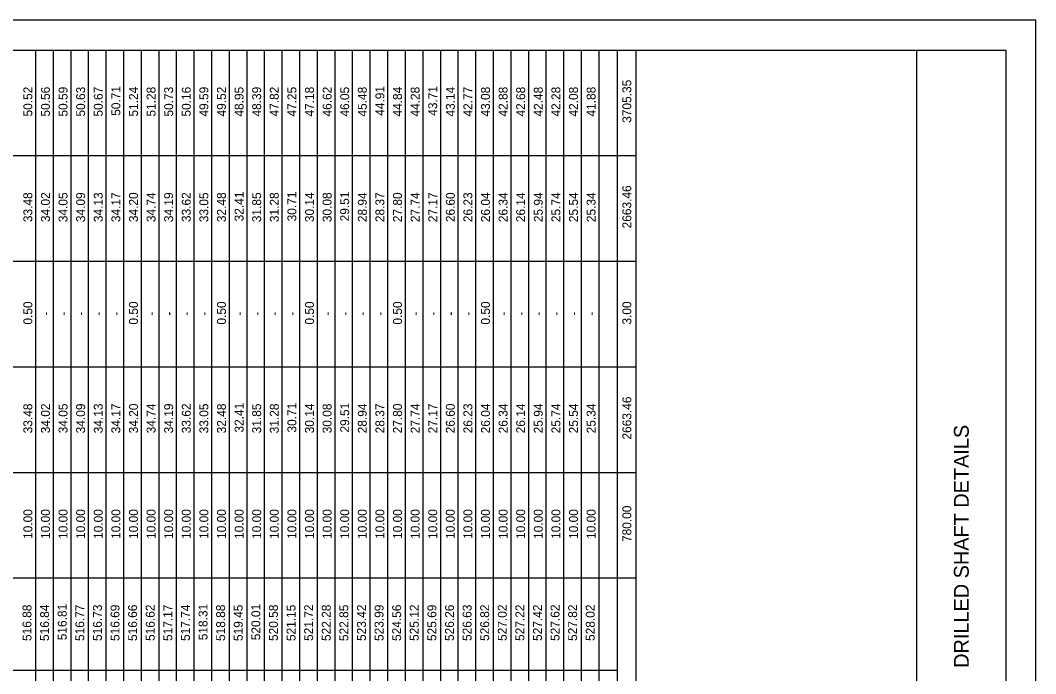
# Model space of a CAD drawing. Extents: x 0 to 34, y 0 to 22.
# Drawn here: x 16.93 to 34, y 11.01 to 22 of the extents above; entities that cross this region are included whole.
import ezdxf

# ---------------------------------------------------------------- set-up
doc = ezdxf.new("R2010")
doc.units = 0
for name, color, linetype in [('SH_Border', 7, 'Continuous'), ('SH_Cut_Line', 7, 'Continuous'), ('SH_Data', 7, 'Continuous'), ('SH_Text', 7, 'Continuous')]:
    doc.layers.add(name, color=color, linetype=linetype)

msp = doc.modelspace()

# ---------------------------------------------------------------- linework, layer by layer
at = {"layer": 'SH_Border'}
msp.add_line((32, 0.5), (32, 21.5), dxfattribs=at)
msp.add_lwpolyline([(1.5, 21.5), (33.5, 21.5), (33.5, 0.5), (1.5, 0.5)], close=True, dxfattribs=at)
at = {"layer": 'SH_Cut_Line'}
msp.add_lwpolyline([(0, 0), (34, 0), (34, 22), (0, 22)], close=True, dxfattribs=at)
at = {"layer": 'SH_Text'}
for p, q in [((1.5, 21.5), (27.28, 21.5)), ((17.187, 0.5), (17.187, 21.5)), ((17.483, 0.5), (17.483, 21.5)), ((17.779, 0.5), (17.779, 21.5)), ((18.075, 0.5), (18.075, 21.5)), ((18.371, 0.5), (18.371, 21.5)), ((18.667, 0.5), (18.667, 21.5)), ((18.963, 0.5), (18.963, 21.5)), ((19.259, 0.5), (19.259, 21.5)), ((19.555, 0.5), (19.555, 21.5)), ((19.851, 0.5), (19.851, 21.5)), ((20.147, 0.5), (20.147, 21.5)), ((20.443, 0.5), (20.443, 21.5)), ((20.739, 0.5), (20.739, 21.5)), ((21.035, 0.5), (21.035, 21.5)), ((21.331, 0.5), (21.331, 21.5)), ((21.627, 0.5), (21.627, 21.5)), ((21.923, 0.5), (21.923, 21.5)), ((22.219, 0.5), (22.219, 21.5)), ((22.515, 0.5), (22.515, 21.5)), ((22.811, 0.5), (22.811, 21.5)), ((23.107, 0.5), (23.107, 21.5)), ((23.403, 0.5), (23.403, 21.5)), ((23.699, 0.5), (23.699, 21.5)), ((23.995, 0.5), (23.995, 21.5)), ((24.291, 0.5), (24.291, 21.5)), ((24.587, 0.5), (24.587, 21.5)), ((24.883, 0.5), (24.883, 21.5)), ((25.179, 0.5), (25.179, 21.5)), ((25.475, 0.5), (25.475, 21.5)), ((25.771, 0.5), (25.771, 21.5)), ((26.067, 0.5), (26.067, 21.5)), ((26.363, 0.5), (26.363, 21.5)), ((26.659, 0.5), (26.659, 21.5)), ((26.969, 0.5), (26.969, 21.5)), ((27.28, 4.851), (27.28, 21.5)), ((1.796, 19.724), (27.28, 19.724)), ((1.796, 17.948), (27.28, 17.948)), ((1.796, 16.172), (27.28, 16.172)), ((1.796, 14.396), (27.28, 14.396)), ((3.572, 12.621), (27.28, 12.621)), ((1.796, 11.067), (26.969, 11.067))]:
    msp.add_line(p, q, dxfattribs=at)

# ---------------------------------------------------------------- texts
at = {"layer": 'SH_Data'}
msp.add_text('DRILLED SHAFT DETAILS', height=0.25, rotation=90, dxfattribs=at).set_placement((32.875, 11.109))
at = {"layer": 'SH_Text'}
for s, height, p in [('50.52', 0.1498, (17.128, 20.382)), ('50.56', 0.1498, (17.424, 20.381)), ('50.59', 0.1498, (17.72, 20.381)), ('50.63', 0.1498, (18.016, 20.381)), ('50.67', 0.1498, (18.312, 20.381)), ('50.71', 0.1498, (18.608, 20.394)), ('51.24', 0.1498, (18.904, 20.381)), ('51.28', 0.1498, (19.2, 20.381)), ('50.73', 0.1498, (19.496, 20.381)), ('50.16', 0.1498, (19.792, 20.381)), ('49.59', 0.1498, (20.088, 20.381)), ('49.52', 0.1498, (20.384, 20.382)), ('48.95', 0.1498, (20.68, 20.38)), ('48.39', 0.1498, (20.976, 20.381)), ('47.82', 0.1498, (21.272, 20.382)), ('47.25', 0.1498, (21.568, 20.38)), ('47.18', 0.1498, (21.864, 20.381)), ('46.62', 0.1498, (22.16, 20.382)), ('46.05', 0.1498, (22.456, 20.38)), ('45.48', 0.1498, (22.752, 20.381)), ('44.91', 0.1498, (23.048, 20.394)), ('44.84', 0.1498, (23.344, 20.381)), ('44.28', 0.1498, (23.64, 20.381)), ('43.71', 0.1498, (23.936, 20.394)), ('43.14', 0.1498, (24.232, 20.381)), ('42.77', 0.1498, (24.527, 20.381)), ('43.08', 0.1498, (24.823, 20.381)), ('42.88', 0.1498, (25.119, 20.381)), ('42.68', 0.1498, (25.415, 20.381)), ('42.48', 0.1498, (25.711, 20.381)), ('42.28', 0.1498, (26.007, 20.381)), ('42.08', 0.1498, (26.303, 20.381)), ('41.88', 0.1498, (26.599, 20.381)), ('3705.35', 0.1498, (27.2, 20.276)), ('2663.46', 0.1498, (27.2, 18.5)), ('33.48', 0.1498, (17.128, 18.605)), ('34.02', 0.1498, (17.424, 18.606)), ('34.05', 0.1498, (17.72, 18.604)), ('34.09', 0.1498, (18.016, 18.605)), ('34.13', 0.1498, (18.312, 18.605)), ('34.17', 0.1498, (18.608, 18.605)), ('34.20', 0.1498, (18.904, 18.605)), ('34.74', 0.1498, (19.2, 18.605)), ('34.19', 0.1498, (19.496, 18.605)), ('33.62', 0.1498, (19.792, 18.606)), ('33.05', 0.1498, (20.088, 18.604)), ('32.48', 0.1498, (20.384, 18.605)), ('32.41', 0.1498, (20.68, 18.618)), ('31.85', 0.1498, (20.976, 18.604)), ('31.28', 0.1498, (21.272, 18.605)), ('30.71', 0.1498, (21.568, 18.618)), ('30.14', 0.1498, (21.864, 18.605)), ('30.08', 0.1498, (22.16, 18.605)), ('29.51', 0.1498, (22.456, 18.618)), ('28.94', 0.1498, (22.752, 18.605)), ('28.37', 0.1498, (23.048, 18.605)), ('27.80', 0.1498, (23.344, 18.605)), ('27.74', 0.1498, (23.64, 18.605)), ('27.17', 0.1498, (23.936, 18.605)), ('26.60', 0.1498, (24.232, 18.605)), ('26.23', 0.1498, (24.527, 18.605)), ('26.04', 0.1498, (24.823, 18.605)), ('26.34', 0.1498, (25.119, 18.605)), ('26.14', 0.1498, (25.415, 18.605)), ('25.94', 0.1498, (25.711, 18.605)), ('25.74', 0.1498, (26.007, 18.605)), ('25.54', 0.1498, (26.303, 18.605)), ('25.34', 0.1498, (26.599, 18.605)), ('0.50', 0.1498, (17.128, 16.882)), ('0.50', 0.1498, (18.904, 16.882)), ('0.50', 0.1498, (20.384, 16.882)), ('0.50', 0.1498, (21.864, 16.882)), ('0.50', 0.1498, (23.344, 16.882)), ('0.50', 0.1498, (24.823, 16.882)), ('3.00', 0.1498, (27.2, 16.882)), ('-', 0.15, (17.424, 17.032)), ('-', 0.15, (17.72, 17.032)), ('-', 0.15, (18.016, 17.032)), ('-', 0.15, (18.312, 17.032)), ('-', 0.15, (18.608, 17.032)), ('-', 0.15, (19.2, 17.032)), ('-', 0.15, (19.496, 17.032)), ('-', 0.15, (19.792, 17.032)), ('-', 0.15, (20.088, 17.032)), ('-', 0.15, (20.68, 17.032)), ('-', 0.15, (20.976, 17.032)), ('-', 0.15, (21.272, 17.032)), ('-', 0.15, (21.568, 17.032)), ('-', 0.15, (22.16, 17.032)), ('-', 0.15, (22.456, 17.032)), ('-', 0.15, (22.752, 17.032)), ('-', 0.15, (23.048, 17.032)), ('-', 0.15, (23.64, 17.032)), ('-', 0.15, (23.936, 17.032)), ('-', 0.15, (24.232, 17.032)), ('-', 0.15, (24.527, 17.032)), ('-', 0.15, (25.119, 17.032)), ('-', 0.15, (25.415, 17.032)), ('-', 0.15, (25.711, 17.032)), ('-', 0.15, (26.007, 17.032)), ('-', 0.15, (26.303, 17.032)), ('-', 0.15, (26.599, 17.032)), ('33.48', 0.1498, (17.128, 15.053)), ('34.02', 0.1498, (17.424, 15.054)), ('34.05', 0.1498, (17.72, 15.053)), ('34.09', 0.1498, (18.016, 15.053)), ('34.13', 0.1498, (18.312, 15.053)), ('34.17', 0.1498, (18.608, 15.053)), ('34.20', 0.1498, (18.904, 15.053)), ('34.74', 0.1498, (19.2, 15.053)), ('34.19', 0.1498, (19.496, 15.053)), ('33.62', 0.1498, (19.792, 15.054)), ('33.05', 0.1498, (20.088, 15.053)), ('32.48', 0.1498, (20.384, 15.053)), ('32.41', 0.1498, (20.68, 15.066)), ('31.85', 0.1498, (20.976, 15.053)), ('31.28', 0.1498, (21.272, 15.053)), ('30.71', 0.1498, (21.568, 15.066)), ('30.14', 0.1498, (21.864, 15.053)), ('30.08', 0.1498, (22.16, 15.053)), ('29.51', 0.1498, (22.456, 15.066)), ('28.94', 0.1498, (22.752, 15.053)), ('28.37', 0.1498, (23.048, 15.053)), ('27.80', 0.1498, (23.344, 15.053)), ('27.74', 0.1498, (23.64, 15.053)), ('27.17', 0.1498, (23.936, 15.053)), ('26.60', 0.1498, (24.232, 15.053)), ('26.23', 0.1498, (24.527, 15.053)), ('26.04', 0.1498, (24.823, 15.053)), ('26.34', 0.1498, (25.119, 15.053)), ('26.14', 0.1498, (25.415, 15.053)), ('25.94', 0.1498, (25.711, 15.053)), ('25.74', 0.1498, (26.007, 15.053)), ('25.54', 0.1498, (26.303, 15.053)), ('25.34', 0.1498, (26.599, 15.053)), ('2663.46', 0.1498, (27.2, 14.948)), ('780.00', 0.1498, (27.2, 13.225)), ('10.00', 0.1498, (17.128, 13.277)), ('10.00', 0.1498, (17.424, 13.277)), ('10.00', 0.1498, (17.72, 13.277)), ('10.00', 0.1498, (18.016, 13.277)), ('10.00', 0.1498, (18.312, 13.277)), ('10.00', 0.1498, (18.608, 13.277)), ('10.00', 0.1498, (18.904, 13.277)), ('10.00', 0.1498, (19.2, 13.277)), ('10.00', 0.1498, (19.496, 13.277)), ('10.00', 0.1498, (19.792, 13.277)), ('10.00', 0.1498, (20.088, 13.277)), ('10.00', 0.1498, (20.384, 13.277)), ('10.00', 0.1498, (20.68, 13.277)), ('10.00', 0.1498, (20.976, 13.277)), ('10.00', 0.1498, (21.272, 13.277)), ('10.00', 0.1498, (21.568, 13.277)), ('10.00', 0.1498, (21.864, 13.277)), ('10.00', 0.1498, (22.16, 13.277)), ('10.00', 0.1498, (22.456, 13.277)), ('10.00', 0.1498, (22.752, 13.277)), ('10.00', 0.1498, (23.048, 13.277)), ('10.00', 0.1498, (23.344, 13.277)), ('10.00', 0.1498, (23.64, 13.277)), ('10.00', 0.1498, (23.936, 13.277)), ('10.00', 0.1498, (24.232, 13.277)), ('10.00', 0.1498, (24.527, 13.277)), ('10.00', 0.1498, (24.823, 13.277)), ('10.00', 0.1498, (25.119, 13.277)), ('10.00', 0.1498, (25.415, 13.277)), ('10.00', 0.1498, (25.711, 13.277)), ('10.00', 0.1498, (26.007, 13.277)), ('10.00', 0.1498, (26.303, 13.277)), ('10.00', 0.1498, (26.599, 13.277)), ('516.88', 0.1498, (17.114, 11.56)), ('516.84', 0.1498, (17.41, 11.56)), ('516.81', 0.1498, (17.706, 11.573)), ('516.77', 0.1498, (18.002, 11.56)), ('516.73', 0.1498, (18.298, 11.56)), ('516.69', 0.1498, (18.594, 11.56)), ('516.66', 0.1498, (18.89, 11.56)), ('516.62', 0.1498, (19.186, 11.561)), ('517.17', 0.1498, (19.482, 11.56)), ('517.74', 0.1498, (19.778, 11.56)), ('518.31', 0.1498, (20.074, 11.573)), ('518.88', 0.1498, (20.37, 11.56)), ('519.45', 0.1498, (20.666, 11.559)), ('520.01', 0.1498, (20.962, 11.573)), ('520.58', 0.1498, (21.258, 11.56)), ('521.15', 0.1498, (21.554, 11.559)), ('521.72', 0.1498, (21.85, 11.561)), ('522.28', 0.1498, (22.146, 11.56)), ('522.85', 0.1498, (22.442, 11.559)), ('523.42', 0.1498, (22.738, 11.561)), ('523.99', 0.1498, (23.034, 11.56)), ('524.56', 0.1498, (23.33, 11.56)), ('525.12', 0.1498, (23.626, 11.561)), ('525.69', 0.1498, (23.922, 11.56)), ('526.26', 0.1498, (24.218, 11.56)), ('526.63', 0.1498, (24.514, 11.56)), ('526.82', 0.1498, (24.81, 11.561)), ('527.02', 0.1498, (25.106, 11.561)), ('527.22', 0.1498, (25.402, 11.561)), ('527.42', 0.1498, (25.698, 11.561)), ('527.62', 0.1498, (25.993, 11.561)), ('527.82', 0.1498, (26.289, 11.561)), ('528.02', 0.1498, (26.585, 11.561))]:
    msp.add_text(s, height=height, rotation=90, dxfattribs=at).set_placement(p)

doc.saveas('drawing.dxf')
